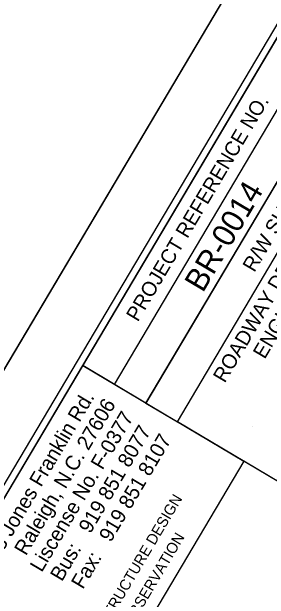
# Model space of a CAD drawing. Extents: x 2137081 to 2142019, y 404041 to 411238.
# Drawn here: x 2140961.3 to 2141049.2, y 410763.2 to 410963.6 of the extents above; entities that cross this region are included whole.
import ezdxf

# ---------------------------------------------------------------- set-up
doc = ezdxf.new("R2010")
doc.units = 0
for name, color, linetype in [('Default', 7, 'Continuous'), ('Prop Guardrail', 7, 'Continuous'), ('Sheet Clip Boundary CELL', 7, 'Continuous'), ('Sheet Cutting Line CELL', 7, 'Continuous'), ('Sheet Data Field CELL', 7, 'Continuous'), ('Sheet Plan And Profile CELL', 7, 'Continuous'), ('Sheet Plot Border Inside CELL', 7, 'Continuous'), ('Sheet Plot Border Outside CELL', 7, 'Continuous')]:
    doc.layers.add(name, color=color, linetype=linetype)

msp = doc.modelspace()

# ---------------------------------------------------------------- linework, layer by layer
at = {"layer": 'Default'}
msp.add_lwpolyline([(2140883.25, 410670.58), (2140985.54, 410842.92), (2141040.49, 410810.3), (2140938.2, 410637.97)], close=True, dxfattribs=at)
at = {"layer": 'Prop Guardrail'}
msp.add_line((2141043.5, 410821.97), (2141043.5, 410821.97), dxfattribs=at)
at = {"layer": 'Sheet Clip Boundary CELL'}
msp.add_lwpolyline([(2140795, 409444.32), (2141473.2, 410586.96), (2141453.94, 410598.39), (2141513.05, 410697.97), (2141213, 410886.12), (2141134.78, 410754.33), (2141040.49, 410810.3), (2140938.2, 410637.97), (2140883.25, 410670.58), (2140322.04, 409725.04)], close=True, dxfattribs=at)
at = {"layer": 'Sheet Cutting Line CELL'}
msp.add_line((2141076.97, 411041.05), (2140217.7, 409593.35), dxfattribs=at)
at = {"layer": 'Sheet Plan And Profile CELL'}
for p, q in [((2140996.33, 410836.51), (2141098.43, 411008.54)), ((2141007.08, 410830.13), (2141109.18, 411002.16)), ((2141007.08, 410830.13), (2141017.83, 410823.75))]:
    msp.add_line(p, q, dxfattribs=at)
for points in [[(2141087.64, 411014.95), (2140322.04, 409725.04), (2141224.97, 409189.12), (2141990.57, 410479.02)], [(2140985.54, 410842.92), (2141087.64, 411014.95), (2141109.18, 411002.16), (2141007.08, 410830.13)], [(2141017.83, 410823.75), (2141068.89, 410909.79), (2141165.63, 410852.37), (2141114.57, 410766.33)]]:
    msp.add_lwpolyline(points, close=True, dxfattribs=at)
at = {"layer": 'Sheet Plot Border Inside CELL'}
msp.add_lwpolyline([(2141148.77, 409055.84), (2141999.1, 410488.49), (2141091.87, 411026.97), (2140241.54, 409594.32)], close=True, dxfattribs=at)
at = {"layer": 'Sheet Plot Border Outside CELL'}
msp.add_lwpolyline([(2141159.33, 409034.46), (2142018.6, 410482.16), (2141076.97, 411041.05), (2140217.7, 409593.35)], close=True, dxfattribs=at)

# ---------------------------------------------------------------- texts
at = {"layer": 'Default'}
for s, height, p in [('1223 Jones Franklin Rd.', 5.01, (2140952.68, 410769.83)), ('Raleigh, N.C. 27606', 5.01, (2140966.17, 410777.84)), ('Liscense No. F-0377', 5.01, (2140971.54, 410772.17)), ('Bus:   919 851 8077', 5.01, (2140978.42, 410769.02)), ('Fax:   919 851 8107', 5.01, (2140985.59, 410766.39)), ('TRANSPORTATION PLANNING/DESIGN - BRIDGE/STRUCTURE DESIGN', 3.674, (2140934.41, 410653.94)), ('CIVIL/SITE DESIGN - GIS/GPS - CONSTRUCTION OBSERVATION', 3.674, (2140943.82, 410655.39))]:
    msp.add_text(s, height=height, rotation=59.3093, dxfattribs=at).set_placement(p)
at = {"layer": 'Sheet Data Field CELL'}
msp.add_text('BR-0014', height=7.75, rotation=59.3093, dxfattribs=at).set_placement((2141026.52, 410867.49))
at = {"layer": 'Sheet Plan And Profile CELL'}
for s, height, p in [('PROJECT REFERENCE NO.', 5.0001, (2141004.35, 410857.57)), ('R/W SHEET NO.', 5.0001, (2141044.08, 410874.45)), ('ROADWAY DESIGN', 5.0001, (2141034, 410836.71)), ('ENGINEER', 5, (2141047.62, 410844.85))]:
    msp.add_text(s, height=height, rotation=59.3093, dxfattribs=at).set_placement(p)

doc.saveas('drawing.dxf')
